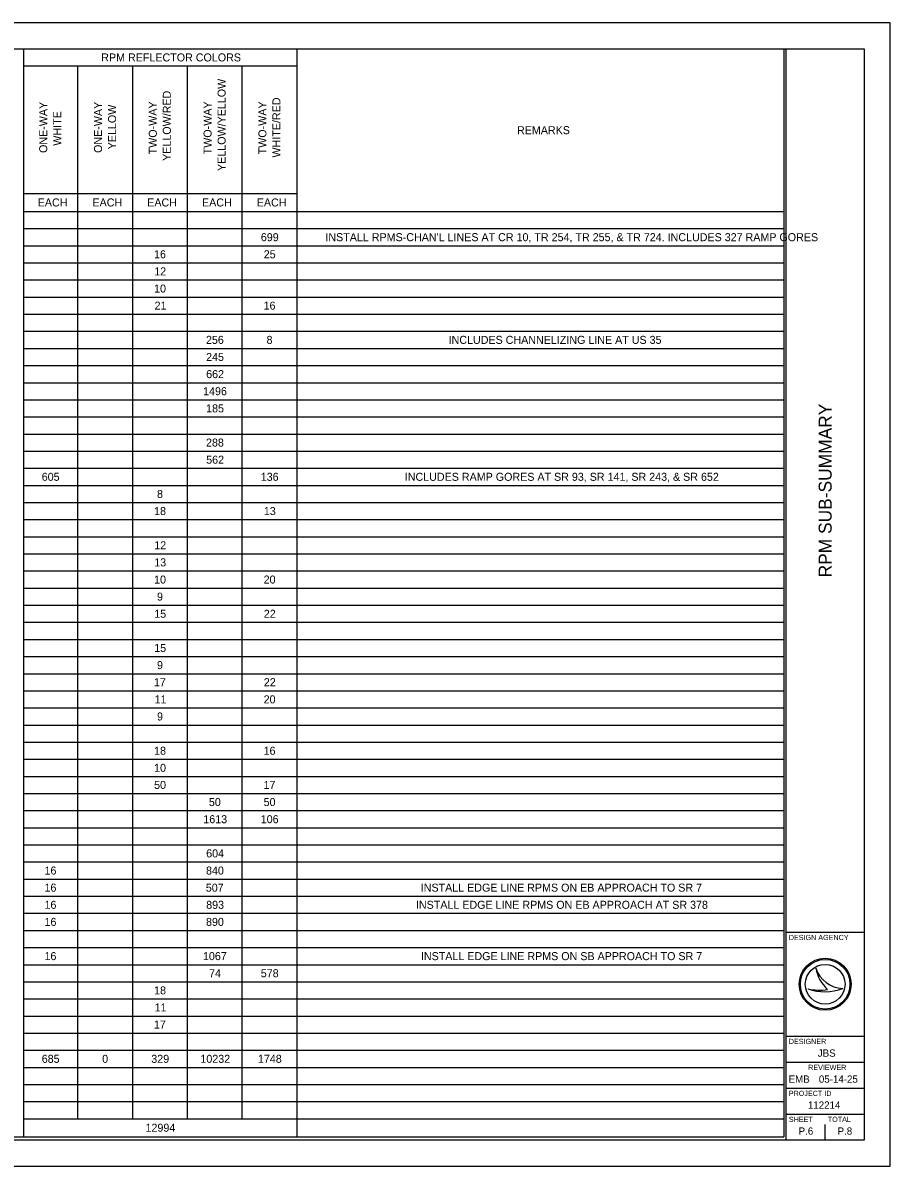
# Model space of a CAD drawing. Extents: x 0 to 34, y 0 to 22.
# Drawn here: x 17.31 to 34, y 0 to 22 of the extents above; entities that cross this region are included whole.
import ezdxf

# ---------------------------------------------------------------- set-up
doc = ezdxf.new("R2010")
doc.units = 0
for name, color, linetype in [('Default', 7, 'Continuous'), ('SH_Border', 7, 'Continuous'), ('SH_Cut_Line', 7, 'Continuous'), ('SH_Data', 7, 'Continuous')]:
    doc.layers.add(name, color=color, linetype=linetype)

msp = doc.modelspace()

# ---------------------------------------------------------------- linework, layer by layer
at = {"layer": 'Default'}
for p, q in [((15.193, 21.5), (17.323, 21.5)), ((17.301, 21.5), (31.954, 21.5)), ((17.323, 21.5), (17.323, 0.566)), ((22.582, 21.5), (22.582, 0.566)), ((31.954, 21.5), (31.954, 0.566)), ((17.323, 21.171), (22.582, 21.171)), ((18.366, 21.171), (18.366, 0.912)), ((19.42, 21.171), (19.42, 0.912)), ((20.474, 21.171), (20.474, 0.912)), ((21.528, 21.171), (21.528, 0.912)), ((17.323, 18.716), (22.582, 18.716)), ((17.323, 18.371), (31.954, 18.371)), ((17.323, 18.041), (31.954, 18.041)), ((17.323, 17.712), (31.954, 17.712)), ((17.323, 17.382), (31.954, 17.382)), ((17.323, 17.053), (31.954, 17.053)), ((17.323, 16.724), (31.954, 16.724)), ((17.323, 16.394), (31.954, 16.394)), ((17.323, 16.065), (31.954, 16.065)), ((17.323, 15.735), (31.954, 15.735)), ((17.323, 15.406), (31.954, 15.406)), ((17.323, 15.076), (31.954, 15.076)), ((17.323, 14.747), (31.954, 14.747)), ((17.323, 14.418), (31.954, 14.418)), ((17.323, 14.088), (31.954, 14.088)), ((17.323, 13.759), (31.954, 13.759)), ((17.323, 13.429), (31.954, 13.429)), ((17.323, 13.1), (31.954, 13.1)), ((17.323, 12.771), (31.954, 12.771)), ((17.323, 12.441), (31.954, 12.441)), ((17.323, 12.112), (31.954, 12.112)), ((17.323, 11.782), (31.954, 11.782)), ((17.323, 11.453), (31.954, 11.453)), ((17.323, 11.124), (31.954, 11.124)), ((17.323, 10.794), (31.954, 10.794)), ((17.323, 10.465), (31.954, 10.465)), ((17.323, 10.135), (31.954, 10.135)), ((17.323, 9.806), (31.954, 9.806)), ((17.323, 9.476), (31.954, 9.476)), ((17.323, 9.147), (31.954, 9.147)), ((17.323, 8.818), (31.954, 8.818)), ((17.323, 8.488), (31.954, 8.488)), ((17.323, 8.159), (31.954, 8.159)), ((17.323, 7.829), (31.954, 7.829)), ((17.323, 7.5), (31.954, 7.5)), ((17.323, 7.171), (31.954, 7.171)), ((17.323, 6.841), (31.954, 6.841)), ((17.323, 6.512), (31.954, 6.512)), ((17.323, 6.182), (31.954, 6.182)), ((17.323, 5.853), (31.954, 5.853)), ((17.323, 5.524), (31.954, 5.524)), ((17.323, 5.194), (31.954, 5.194)), ((17.323, 4.865), (31.954, 4.865)), ((17.323, 4.535), (31.954, 4.535)), ((17.323, 4.206), (31.954, 4.206)), ((17.323, 3.876), (31.954, 3.876)), ((17.323, 3.547), (31.954, 3.547)), ((17.323, 3.218), (31.954, 3.218)), ((17.323, 2.888), (31.954, 2.888)), ((17.323, 2.559), (31.954, 2.559)), ((17.323, 2.229), (31.954, 2.229)), ((17.323, 1.9), (31.954, 1.9)), ((17.323, 1.571), (31.954, 1.571)), ((17.323, 1.241), (31.954, 1.241)), ((17.323, 0.912), (31.954, 0.912)), ((15.193, 0.566), (17.323, 0.566)), ((17.301, 0.566), (31.954, 0.566))]:
    msp.add_line(p, q, dxfattribs=at)
at = {"layer": 'SH_Border'}
for p, q in [((32, 0.5), (32, 21.5)), ((32, 4.5), (33.5, 4.5)), ((32, 2.5), (33.5, 2.5)), ((32, 2), (33.5, 2)), ((32, 1.5), (33.5, 1.5)), ((32, 1), (33.5, 1))]:
    msp.add_line(p, q, dxfattribs=at)
msp.add_lwpolyline([(1.5, 21.5), (33.5, 21.5), (33.5, 0.5), (1.5, 0.5)], close=True, dxfattribs=at)
at = {"layer": 'SH_Cut_Line'}
msp.add_lwpolyline([(0, 0), (34, 0), (34, 22), (0, 22)], close=True, dxfattribs=at)
at = {"layer": 'SH_Data'}
for p, q in [((32.567, 3.81), (32.567, 3.81)), ((32.417, 3.41), (32.417, 3.41)), ((32.75, 3.5), (32.75, 3.5)), ((33.087, 3.419), (33.087, 3.419)), ((32.375, 0.675), (32.375, 0.675)), ((32.75, 0.5), (32.75, 0.8))]:
    msp.add_line(p, q, dxfattribs=at)
for radius in [0.5, 0.477, 0.477, 0.382]:
    msp.add_circle((32.75, 3.5), radius, dxfattribs=at)
for centre, radius, start, end in [((33.116, 3.998), 0.58, 198.9257, 198.9319), ((33.347, 3.97), 0.796, 191.6379, 191.6421), ((33.116, 3.998), 0.58, 198.9319, 267.1657), ((33.347, 3.97), 0.796, 191.6421, 226.0947), ((32.739, 4.37), 1.013, 251.4576, 290.0832), ((32.648, 4.654), 1.266, 259.4964, 259.4995), ((32.739, 4.37), 1.013, 251.4527, 251.4576), ((32.648, 4.654), 1.266, 259.4995, 276.6672)]:
    msp.add_arc(centre, radius, start, end, dxfattribs=at)

# ---------------------------------------------------------------- texts
at = {"layer": 'Default'}
for s, p in [('RPM REFLECTOR COLORS', (18.82, 21.258)), ('REMARKS', (26.82, 19.858)), ('EACH', (17.597, 18.467)), ('EACH', (18.651, 18.467)), ('EACH', (19.705, 18.467)), ('EACH', (20.759, 18.467)), ('EACH', (21.813, 18.467)), ('699', (21.891, 17.799)), ("INSTALL RPMS-CHAN'L LINES AT CR 10, TR 254, TR 255, & TR 724. INCLUDES 327 RAMP GORES", (23.133, 17.799)), ('16', (19.836, 17.47)), ('25', (21.947, 17.47)), ('12', (19.84, 17.141)), ('10', (19.837, 16.811)), ('21', (19.846, 16.482)), ('16', (21.944, 16.482)), ('256', (20.835, 15.823)), ('8', (22.001, 15.823)), ('INCLUDES CHANNELIZING LINE AT US 35', (25.504, 15.823)), ('245', (20.838, 15.494)), ('662', (20.839, 15.164)), ('1496', (20.78, 14.835)), ('185', (20.838, 14.505)), ('288', (20.836, 13.847)), ('562', (20.839, 13.517)), ('605', (17.675, 13.188)), ('136', (21.889, 13.188)), ('INCLUDES RAMP GORES AT SR 93, SR 141, SR 243, & SR 652', (24.661, 13.188)), ('8', (19.893, 12.858)), ('18', (19.837, 12.529)), ('13', (21.949, 12.529)), ('12', (19.84, 11.87)), ('13', (19.84, 11.541)), ('10', (19.837, 11.211)), ('20', (21.945, 11.211)), ('9', (19.893, 10.882)), ('15', (19.839, 10.552)), ('22', (21.948, 10.552)), ('15', (19.839, 9.894)), ('9', (19.893, 9.564)), ('17', (19.833, 9.235)), ('22', (21.948, 9.235)), ('11', (19.846, 8.905)), ('20', (21.945, 8.905)), ('9', (19.893, 8.576)), ('18', (19.837, 7.917)), ('16', (21.944, 7.917)), ('10', (19.837, 7.588)), ('50', (19.837, 7.258)), ('17', (21.942, 7.258)), ('50', (20.891, 6.929)), ('50', (21.945, 6.929)), ('1613', (20.784, 6.599)), ('106', (21.889, 6.599)), ('604', (20.839, 5.941)), ('16', (17.728, 5.611)), ('840', (20.836, 5.611)), ('16', (17.728, 5.282)), ('507', (20.832, 5.282)), ('INSTALL EDGE LINE RPMS ON EB APPROACH TO SR 7', (24.968, 5.282)), ('16', (17.728, 4.952)), ('893', (20.839, 4.952)), ('INSTALL EDGE LINE RPMS ON EB APPROACH AT SR 378', (24.875, 4.952)), ('16', (17.728, 4.623)), ('890', (20.836, 4.623)), ('16', (17.728, 3.964)), ('1067', (20.777, 3.964)), ('INSTALL EDGE LINE RPMS ON SB APPROACH TO SR 7', (24.971, 3.964)), ('74', (20.895, 3.635)), ('578', (21.89, 3.635)), ('18', (19.837, 3.305)), ('11', (19.846, 2.976)), ('17', (19.833, 2.647)), ('685', (17.675, 1.988)), ('0', (18.838, 1.988)), ('329', (19.783, 1.988)), ('10232', (20.728, 1.988)), ('1748', (21.835, 1.988)), ('12994', (19.672, 0.662))]:
    msp.add_text(s, height=0.154, dxfattribs=at).set_placement(p)
for s, p in [('YELLOW/YELLOW', (21.213, 19.15)), ('YELLOW/RED', (20.159, 19.344)), ('ONE-WAY ', (17.781, 19.497)), ('ONE-WAY', (18.835, 19.497)), ('TWO-WAY', (19.889, 19.47)), ('TWO-WAY', (20.943, 19.47)), ('TWO-WAY', (21.998, 19.47)), ('WHITE/RED', (22.267, 19.409)), ('WHITE', (18.051, 19.636)), ('YELLOW', (19.105, 19.567))]:
    msp.add_text(s, height=0.154, rotation=90, dxfattribs=at).set_placement(p)
at = {"layer": 'SH_Data'}
msp.add_text('RPM SUB-SUMMARY', height=0.25, rotation=90, dxfattribs=at).set_placement((32.875, 11.329))
for s, height, p in [('DESIGN AGENCY', 0.1, (32.05, 4.35)), ('DESIGNER', 0.1, (32.05, 2.35)), ('JBS', 0.14, (32.608, 2.105)), ('REVIEWER', 0.1, (32.422, 1.85)), ('EMB', 0.14, (32.047, 1.605)), ('05-14-25', 0.14, (32.629, 1.605)), ('PROJECT ID', 0.1, (32.05, 1.35)), ('112214', 0.14, (32.418, 1.105)), ('SHEET', 0.1, (32.05, 0.85)), ('TOTAL', 0.1, (32.8, 0.85)), ('P.6', 0.14, (32.239, 0.605)), ('P.8', 0.14, (32.989, 0.605))]:
    msp.add_text(s, height=height, dxfattribs=at).set_placement(p)

doc.saveas('drawing.dxf')
